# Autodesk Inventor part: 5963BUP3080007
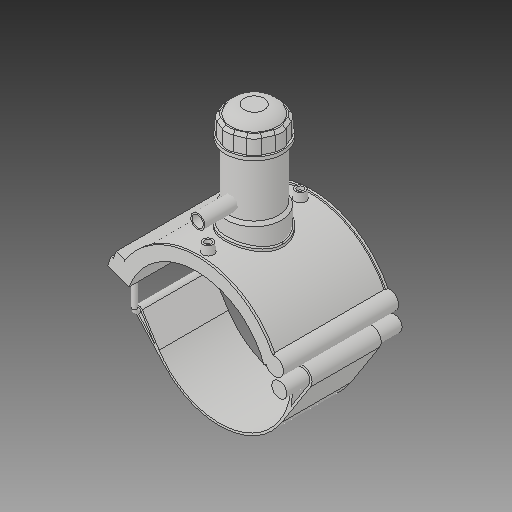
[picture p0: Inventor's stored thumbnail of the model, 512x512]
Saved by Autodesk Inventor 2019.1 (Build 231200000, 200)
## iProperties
Created: 2017-07
Part Number: 5963BUP3080007
Material: Generic
Description: PLASSON TAPPING SADDLE 8''IPS x 3/4''CTS
Document SubType Name: Modeling
Designer: KIM
Density: 1 g/cm^3
Appearance: Default
Author: KIM
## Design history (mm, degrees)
derived "5963BBP_5963BUP.ipt"
feature "Solid1::5963BBP_5963BUP.ipt"
feature "Solid2::5963BBP_5963BUP.ipt"
feature "Solid3::5963BBP_5963BUP.ipt"
tag "TaggingFeature1"
body "Solid1"
body "Solid2"
body "Solid3"
other parameters: "d0" = 218.7, "d2" = 269.748, "d3" = 54.675, "d4" = 176.022, "d5" = 0, "d6" = 0.1, "d8" = 0, "d19" = 6, "d20" = 6, "d21" = 105.6132, "d23" = 0, "d24" = 52.8066, "d26" = 0, "d27" = 3, "d28" = 3, "d29" = 3, "d30" = 72.9, "d31" = 6, "d32" = 0, "d33" = 0, "d34" = 0.6, "d40" = 131.91984, "d41" = 87.48, "d43" = 0, "d45" = 0, "d47" = 232.4592, "d70" = 15, "d72" = 0, "d73" = 6, "d75" = 5, "d76" = 0, "d77" = 10.935, "d78" = 139.35, "d79" = 15, "d80" = 70.4088, "d82" = 5 deg, "d84" = 4, "d85" = 14, "d86" = 0, "d87" = 3, "d88" = 0, "d89" = 1, "d90" = 1, "d91" = 140.8176, "d92" = 0, "d93" = 0.5, "d94" = 115.10526, "d96" = 258.76584, "d97" = 3.52044, "d98" = 0, "d102" = 2.187, "d120" = 140 deg, "d121" = 24.228, "d122" = 20 deg, "d123" = 507.384, "d124" = 152.2152, "d126" = 0, "d143" = 225.261, "d145" = 26.91692, "d149" = 3.2805, "d150" = 29.60862, "d153" = 176.022, "d154" = 0, "d156" = 126.846, "d157" = 160 deg, "d159" = 6.9984, "d161" = 3.2805, "d162" = 105.6132, "d163" = 0, "d164" = 109.35, "d167" = 21.87, "d168" = 123.7522, "d170" = 3.2805, "d172" = 0, "d173" = 1, "d175" = 109.35, "d176" = 20 deg, "d177" = 15.309, "d178" = 34.992, "d180" = 0, "d183" = 13.9968, "d184" = 12.2472, "d185" = 57.20715, "d186" = 57.20715, "d187" = 126.846, "d188" = 10.4976, "d189" = 15.309, "d190" = 0, "d191" = 190.269, "d193" = 6.9984, "d194" = 6.16077, "d195" = 90 deg, "d197" = 0, "d199" = 0, "d200" = 17.496, "d202" = 0, "d203" = 177.038, "d204" = 83.106, "d205" = 61.236, "d206" = 74.358, "d207" = 132.7785, "d208" = 138.08964, "d209" = 164.64534, "d210" = 75.2328, "d211" = 87.48, "d212" = 69.984, "d213" = 48.5766, "d216" = 0, "d217" = 21.87, "d218" = 21.87, "d219" = 4.374, "d222" = 218.7, "d224" = 0, "d225" = 65.024, "d226" = 22.1, "d227" = 17.68, "d228" = 86.106, "d230" = 4.374, "d_" = 218.7, "B_" = 179.832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
